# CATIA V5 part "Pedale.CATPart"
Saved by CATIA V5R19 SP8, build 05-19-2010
Part number: Pedale
Bounding box of the stored display mesh (mm): x 0 to 80, y -40 to 40, z -10 to 10
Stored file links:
  C:\Users\schneidp\Desktop\Manikan\V5R19\Pedale.CATPart
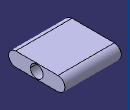
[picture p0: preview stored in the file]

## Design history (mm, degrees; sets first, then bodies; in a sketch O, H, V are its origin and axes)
Body1 (main body)
  Sketch1 on yz-plane, origin (0, 0, 0), H (0, 1, 0), V (0, 0, 1)
    construction line L1 (-30, 0) -> (30, 0)
    point P1 (-30, 0)
    point P2 (30, 0)
    line L2 (-30, 10) -> (30, 10)
    line L3 (30, -10) -> (-30, -10)
    arc A1 centre (30, 0) radius 10 from (30, 10) to (30, -10) cw
    arc A2 centre (-30, 0) radius 10 from (-30, -10) to (-30, 10) cw
    circle A3 centre (0, 0) radius 9
    distance L1 L2 = 10
    distance P2 P1 = 60
    distance V P2 = 30
    radius A3 = 9
    coincidence: P1 H
    horizontal: L1 H
    tangency: A1 L2, A2 L2, A1 L3, A2 L3
  Pad1: profile Sketch1, direction (1, 0, 0), length 80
